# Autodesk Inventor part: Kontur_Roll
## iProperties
Created: 2008-12
Part Number: Kontur_Roll
Material: Default
Document SubType Name: Sheet Metal
Designer: Designer
Density: 1 g/cm^3
Sheet Metal Rule: Default_mm
Author: Designer
